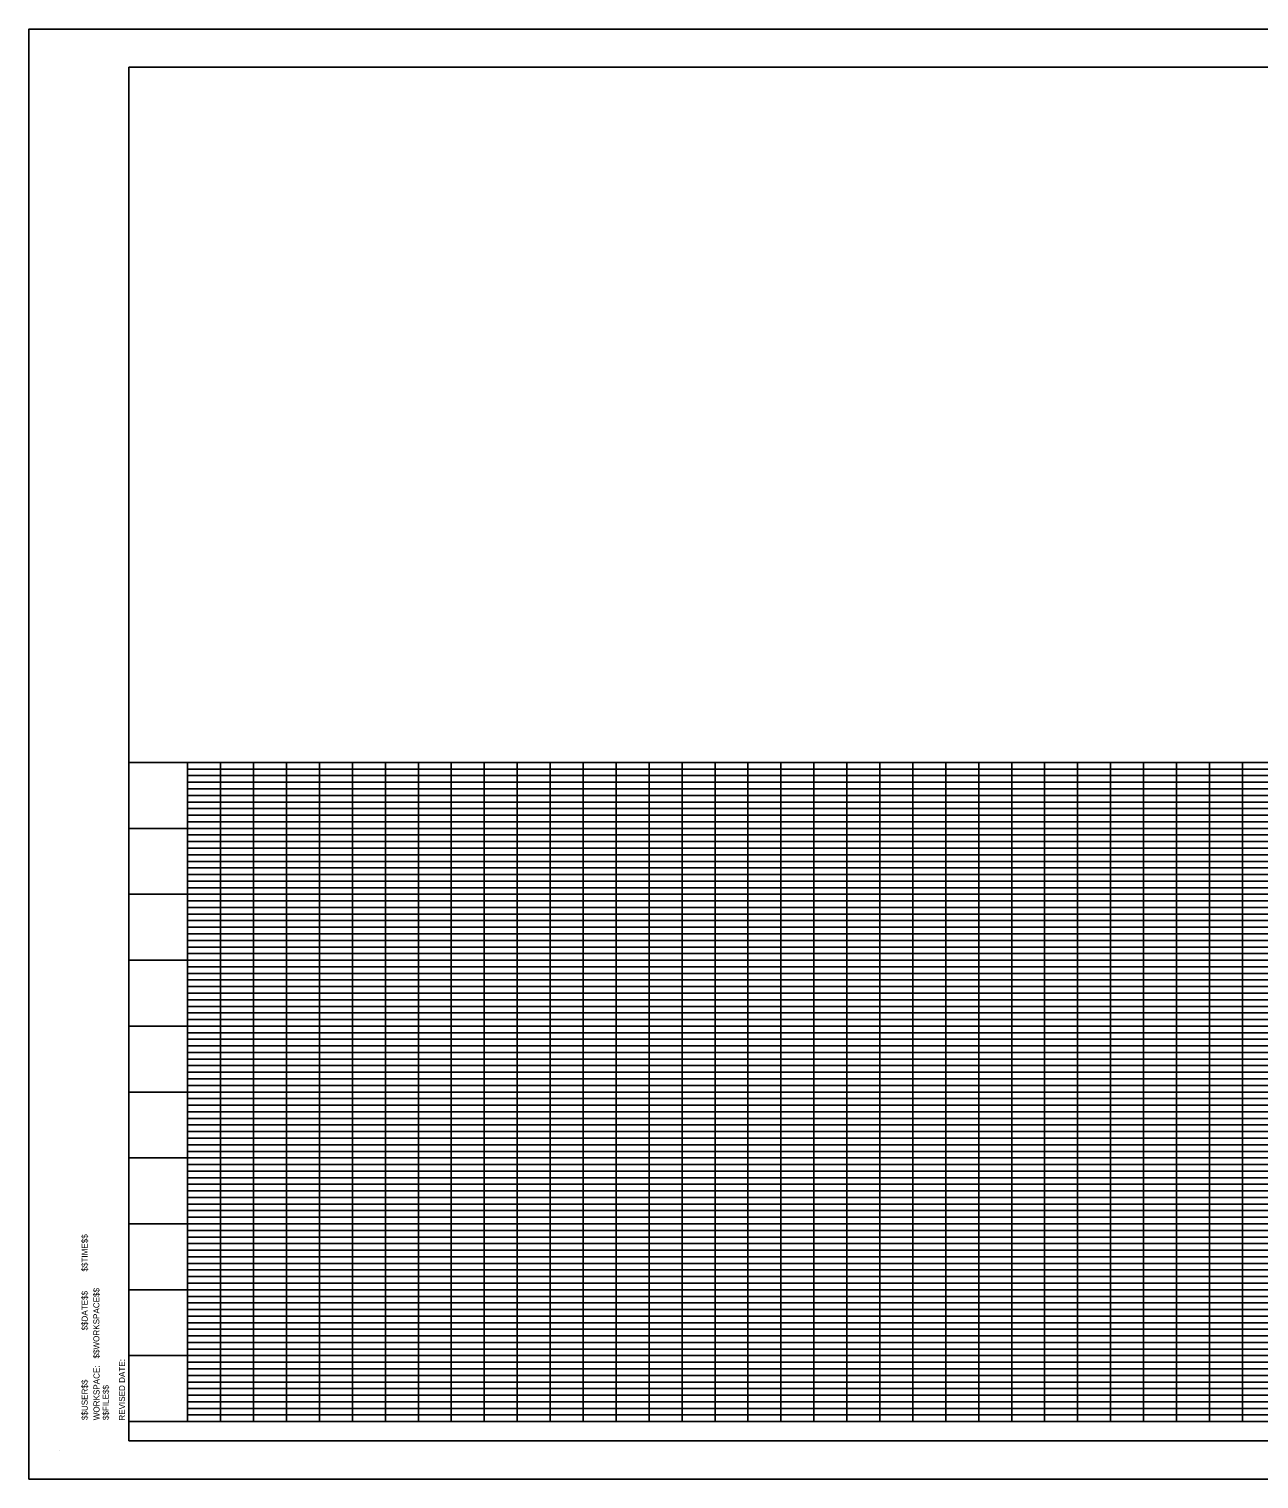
# Model space of a CAD drawing. Extents: x 759422 to 1448857, y 1662254 to 2059437.
# Drawn here: x 1446988 to 1447921, y 2058337 to 2059437 of the extents above; entities that cross this region are included whole.
import ezdxf

# ---------------------------------------------------------------- set-up
doc = ezdxf.new("R2010")
doc.units = 0
doc.layers.add('1', color=7, linetype='Continuous')

msp = doc.modelspace()

# ---------------------------------------------------------------- linework, layer by layer
at = {"layer": '1'}
for p, q in [((1447064.2, 2059407.7), (1448659.6, 2059407.7)), ((1447064.2, 2058365.4), (1447064.2, 2059407.7)), ((1448659.6, 2058880.1), (1447064.2, 2058880.1)), ((1447108.7, 2058380.1), (1447108.7, 2058880.1)), ((1448608.7, 2058875.1), (1447108.7, 2058875.1)), ((1448608.7, 2058870.1), (1447108.7, 2058870.1)), ((1447133.7, 2058380.1), (1447133.7, 2058880.1)), ((1447158.7, 2058380.1), (1447158.7, 2058880.1)), ((1447183.7, 2058380.1), (1447183.7, 2058880.1)), ((1447208.7, 2058380.1), (1447208.7, 2058880.1)), ((1447233.7, 2058380.1), (1447233.7, 2058880.1)), ((1447258.7, 2058380.1), (1447258.7, 2058880.1)), ((1447283.7, 2058380.1), (1447283.7, 2058880.1)), ((1447308.7, 2058380.1), (1447308.7, 2058880.1)), ((1447333.7, 2058380.1), (1447333.7, 2058880.1)), ((1447358.7, 2058380.1), (1447358.7, 2058880.1)), ((1447383.7, 2058380.1), (1447383.7, 2058880.1)), ((1447408.7, 2058380.1), (1447408.7, 2058880.1)), ((1447433.7, 2058380.1), (1447433.7, 2058880.1)), ((1447458.7, 2058380.1), (1447458.7, 2058880.1)), ((1447483.7, 2058380.1), (1447483.7, 2058880.1)), ((1447508.7, 2058380.1), (1447508.7, 2058880.1)), ((1447533.7, 2058380.1), (1447533.7, 2058880.1)), ((1447558.7, 2058380.1), (1447558.7, 2058880.1)), ((1447583.7, 2058380.1), (1447583.7, 2058880.1)), ((1447608.7, 2058380.1), (1447608.7, 2058880.1)), ((1447633.7, 2058380.1), (1447633.7, 2058880.1)), ((1447658.7, 2058380.1), (1447658.7, 2058880.1)), ((1447683.7, 2058380.1), (1447683.7, 2058880.1)), ((1447708.7, 2058380.1), (1447708.7, 2058880.1)), ((1447733.7, 2058380.1), (1447733.7, 2058880.1)), ((1447758.7, 2058380.1), (1447758.7, 2058880.1)), ((1447783.7, 2058380.1), (1447783.7, 2058880.1)), ((1447808.7, 2058380.1), (1447808.7, 2058880.1)), ((1447833.7, 2058380.1), (1447833.7, 2058880.1)), ((1447858.7, 2058380.1), (1447858.7, 2058880.1)), ((1447883.7, 2058380.1), (1447883.7, 2058880.1)), ((1447908.7, 2058380.1), (1447908.7, 2058880.1)), ((1448608.7, 2058865.1), (1447108.7, 2058865.1)), ((1448608.7, 2058860.1), (1447108.7, 2058860.1)), ((1448608.7, 2058855.1), (1447108.7, 2058855.1)), ((1448608.7, 2058850.1), (1447108.7, 2058850.1)), ((1448608.7, 2058845.1), (1447108.7, 2058845.1)), ((1448608.7, 2058840.1), (1447108.7, 2058840.1)), ((1448659.6, 2058830.1), (1447064.2, 2058830.1)), ((1448608.7, 2058835.1), (1447108.7, 2058835.1)), ((1448608.7, 2058825.1), (1447108.7, 2058825.1)), ((1448608.7, 2058820.1), (1447108.7, 2058820.1)), ((1448608.7, 2058815.1), (1447108.7, 2058815.1)), ((1448608.7, 2058810.1), (1447108.7, 2058810.1)), ((1448608.7, 2058805.1), (1447108.7, 2058805.1)), ((1448608.7, 2058800.1), (1447108.7, 2058800.1)), ((1448608.7, 2058795.1), (1447108.7, 2058795.1)), ((1448608.7, 2058790.1), (1447108.7, 2058790.1)), ((1448608.7, 2058785.1), (1447108.7, 2058785.1)), ((1448659.6, 2058780.1), (1447064.2, 2058780.1)), ((1448608.7, 2058775.1), (1447108.7, 2058775.1)), ((1448608.7, 2058770.1), (1447108.7, 2058770.1)), ((1448608.7, 2058765.1), (1447108.7, 2058765.1)), ((1448608.7, 2058760.1), (1447108.7, 2058760.1)), ((1448608.7, 2058755.1), (1447108.7, 2058755.1)), ((1448608.7, 2058750.1), (1447108.7, 2058750.1)), ((1448608.7, 2058745.1), (1447108.7, 2058745.1)), ((1448608.7, 2058740.1), (1447108.7, 2058740.1)), ((1448659.6, 2058730.1), (1447064.2, 2058730.1)), ((1448608.7, 2058735.1), (1447108.7, 2058735.1)), ((1448608.7, 2058725.1), (1447108.7, 2058725.1)), ((1448608.7, 2058720.1), (1447108.7, 2058720.1)), ((1448608.7, 2058715.1), (1447108.7, 2058715.1)), ((1448608.7, 2058710.1), (1447108.7, 2058710.1)), ((1448608.7, 2058705.1), (1447108.7, 2058705.1)), ((1448608.7, 2058700.1), (1447108.7, 2058700.1)), ((1448608.7, 2058695.1), (1447108.7, 2058695.1)), ((1448608.7, 2058690.1), (1447108.7, 2058690.1)), ((1448608.7, 2058685.1), (1447108.7, 2058685.1)), ((1448659.6, 2058680.1), (1447064.2, 2058680.1)), ((1448608.7, 2058675.1), (1447108.7, 2058675.1)), ((1448608.7, 2058670.1), (1447108.7, 2058670.1)), ((1448608.7, 2058665.1), (1447108.7, 2058665.1)), ((1448608.7, 2058660.1), (1447108.7, 2058660.1)), ((1448608.7, 2058655.1), (1447108.7, 2058655.1)), ((1448608.7, 2058650.1), (1447108.7, 2058650.1)), ((1448608.7, 2058645.1), (1447108.7, 2058645.1)), ((1448608.7, 2058640.1), (1447108.7, 2058640.1)), ((1448659.6, 2058630.1), (1447064.2, 2058630.1)), ((1448608.7, 2058635.1), (1447108.7, 2058635.1)), ((1448608.7, 2058625.1), (1447108.7, 2058625.1)), ((1448608.7, 2058620.1), (1447108.7, 2058620.1)), ((1448608.7, 2058615.1), (1447108.7, 2058615.1)), ((1448608.7, 2058610.1), (1447108.7, 2058610.1)), ((1448608.7, 2058605.1), (1447108.7, 2058605.1)), ((1448608.7, 2058600.1), (1447108.7, 2058600.1)), ((1448608.7, 2058595.1), (1447108.7, 2058595.1)), ((1448608.7, 2058590.1), (1447108.7, 2058590.1)), ((1448608.7, 2058585.1), (1447108.7, 2058585.1)), ((1448659.6, 2058580.1), (1447064.2, 2058580.1)), ((1448608.7, 2058575.1), (1447108.7, 2058575.1)), ((1448608.7, 2058570.1), (1447108.7, 2058570.1)), ((1448608.7, 2058565.1), (1447108.7, 2058565.1)), ((1448608.7, 2058560.1), (1447108.7, 2058560.1)), ((1448608.7, 2058555.1), (1447108.7, 2058555.1)), ((1448608.7, 2058550.1), (1447108.7, 2058550.1)), ((1448608.7, 2058545.1), (1447108.7, 2058545.1)), ((1448608.7, 2058540.1), (1447108.7, 2058540.1)), ((1448659.6, 2058530.1), (1447064.2, 2058530.1)), ((1448608.7, 2058535.1), (1447108.7, 2058535.1)), ((1448608.7, 2058525.1), (1447108.7, 2058525.1)), ((1448608.7, 2058520.1), (1447108.7, 2058520.1)), ((1448608.7, 2058515.1), (1447108.7, 2058515.1)), ((1448608.7, 2058510.1), (1447108.7, 2058510.1)), ((1448608.7, 2058505.1), (1447108.7, 2058505.1)), ((1448608.7, 2058500.1), (1447108.7, 2058500.1)), ((1448608.7, 2058495.1), (1447108.7, 2058495.1)), ((1448608.7, 2058490.1), (1447108.7, 2058490.1)), ((1448608.7, 2058485.1), (1447108.7, 2058485.1)), ((1448659.6, 2058480.1), (1447064.2, 2058480.1)), ((1448608.7, 2058475.1), (1447108.7, 2058475.1)), ((1448608.7, 2058470.1), (1447108.7, 2058470.1)), ((1448608.7, 2058465.1), (1447108.7, 2058465.1)), ((1448608.7, 2058460.1), (1447108.7, 2058460.1)), ((1448608.7, 2058455.1), (1447108.7, 2058455.1)), ((1448608.7, 2058450.1), (1447108.7, 2058450.1)), ((1448608.7, 2058445.1), (1447108.7, 2058445.1)), ((1448659.6, 2058430.1), (1447064.2, 2058430.1)), ((1448608.7, 2058440.1), (1447108.7, 2058440.1)), ((1448608.7, 2058435.1), (1447108.7, 2058435.1)), ((1448608.7, 2058425.1), (1447108.7, 2058425.1)), ((1448608.7, 2058420.1), (1447108.7, 2058420.1)), ((1448608.7, 2058415.1), (1447108.7, 2058415.1)), ((1448608.7, 2058410.1), (1447108.7, 2058410.1)), ((1448608.7, 2058405.1), (1447108.7, 2058405.1)), ((1448608.7, 2058400.1), (1447108.7, 2058400.1)), ((1448608.7, 2058395.1), (1447108.7, 2058395.1)), ((1448608.7, 2058390.1), (1447108.7, 2058390.1)), ((1448659.6, 2058380.1), (1447064.2, 2058380.1)), ((1448608.7, 2058385.1), (1447108.7, 2058385.1)), ((1448659.6, 2058365.4), (1447064.2, 2058365.4)), ((1447011.8, 2058357.9), (1447011.8, 2058357.9))]:
    msp.add_line(p, q, dxfattribs=at)
msp.add_lwpolyline([(1448688.4, 2059436.5), (1446988.4, 2059436.5), (1446988.4, 2058336.5), (1448688.4, 2058336.5)], close=True, dxfattribs=at)

# ---------------------------------------------------------------- texts
for s, p in [('$$TIME$$', (1447032.9, 2058493.9)), ('$$DATE$$', (1447032.9, 2058449.2)), ('$$WORKSPACE$$', (1447041.8, 2058427.9)), ('WORKSPACE:', (1447041.9, 2058381.1)), ('REVISED DATE:', (1447061.2, 2058380.8)), ('$$USER$$', (1447032.9, 2058381.2)), ('$$FILE$$', (1447048.9, 2058381.2))]:
    msp.add_text(s, height=4.59, rotation=90, dxfattribs=at).set_placement(p)

doc.saveas('drawing.dxf')
